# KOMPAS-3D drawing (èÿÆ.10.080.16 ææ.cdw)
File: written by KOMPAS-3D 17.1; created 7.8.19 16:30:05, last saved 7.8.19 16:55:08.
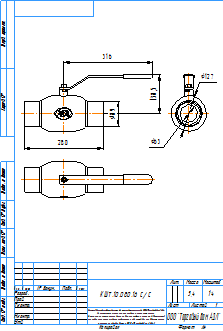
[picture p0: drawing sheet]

Sheet 1: A4, portrait

Title block, sheet 1: name: КШТ.10.080.16 С/С; material: Сталь 20  ГОСТ 1050-2013; mass: 5,4; sheets: 1; sheet format: A4; stored path: \\adlc.lan\data\АДЛ_ПКД\3D-модели\ADL production\Шаровые краны БИВАЛ\КШ_Бивал_серия_10\KOMPAS 2D\КШТ.10.080.16 СС.cdw

Views: Вид 1, Проекционный вид 2, Проекционный вид 3
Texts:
  kka
  adl
  Рама для чертежей
  Лит-Масса-Масштаб
  Материал-Предприятие
  Масштаб
  Изм.
  Лист
  № докум.
  Подп.
  Дата
  Лит.
  Разраб.
  Пров.
  Т.контр.
  Листов
  Внимание! Данный продукт является объектом авторского права ООО «Торговый Дом АДЛ».
  Запрещается изменение, копирование, распространение
  (в том числе путем копирования на другие сайты и ресурсы в Интернете)
  или любое иное использование информации и объектов без предварительного
  согласия правообладателя (ООО «Торговый Дом АДЛ»).
  Н.контр.
  Утв.
  ООО "Торговый дом АДЛ"
  Изменение
  Номер документа
  Подпись
  Обозначение документа
  Наименование изделия
  Масса изделия по ГОСТ 2.109-73
  Порядковый номер листа
  Общее количество листов в документе
  Характер работы, выполненной лицом, подписавшим документ
  Наименование или индекс предприятия, выпускающего документ
  Инв. № подл.
  Подп. и дата
  Взам. инв. №
  Инв. № дубл.
  Инвентарный номер подлинника по ГОСТ 2.501-68
  Подпись принявшего подлинник в отдел технической документации
  Инвентарный номер подлинника, взамен которого выпущен данный подлинник
  Инвентарный номер дубликата по ГОСТ 2.502-68
  Подпись принявшего дубликат в отдел технической документации
  Справ. №
  Перв. примен.
  Обозначение документа, взамен или на основании которого выпущен данный документ
  Обозначение документа, в котором впервые записан данный документ
  Подпись лица, копировавшего чертеж
  Обозначение формата листа
  !Рама для чертежа
Dimensions and other numbers on the sheet: 280; 89; 138,5; 316; 127; 63; 1:4; 1; 5,4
